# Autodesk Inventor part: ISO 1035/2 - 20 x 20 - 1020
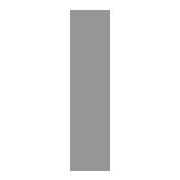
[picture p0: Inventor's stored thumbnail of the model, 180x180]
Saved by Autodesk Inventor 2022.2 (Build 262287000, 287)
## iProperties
IsCustomPart: 1
Created: 2021-02
Part Number: ISO 1035/2 - 20 x 20 - 1020
Material: Acciaio, Dolce
Description: Barre in acciaio laminate a caldo - Parte 2: barre quadre
Document SubType Name: Modeling
Standard: ISO 1035/2
Designer: 18907419
Standard Revision: First edition 1980-10-15
Standards Organization: ISO
Language: it-IT
Size Designation: 20x 20
Categories: <MemberInstance><Categories><Category DisplayName="Forme strutturali" InternalName="089c4875-fa83-4c05-b084-43b9cc11f5ed" Mnemonic="GRDR"><CategoryParameter Dis
Stock Number: 20x 20
Density: 7.85 g/cm^3
Appearance: Semilucidato
_CCFamilyMember: 168
_CCFamilyDisplayName: ISO 1035/2 - 1980 - Barre in acciaio laminate a caldo - Parte 2: barre quadre
_FrameMemberDoc: Frame Member File
_Version: 15.0.0
_GetPNFromCC: 1
G_L: 1020,000 mm
G_W: 20,000 mm
G_H: 20,000 mm
+9CC89346-D58E-49AB-A0AD-2FBC8E4EAC78+CUTDETAIL1: Angolo retto 45,00 gr
+2362145C-A886-4DE2-AF4E-FECAC0FDEC64+CUTDETAIL2: Angolo retto 45,00 gr
Author: 18907419
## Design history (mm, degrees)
node "Piano iniziale"
node "Piano finale"
sketch "Schizzo"
  geometry: L1 (10, -10)-(-10, -10); L2 (-10, -10)-(-10, 10); L3 (-10, 10)-(10, 10); L4 (10, 10)-(10, -10); L5 (-6, 0)-(8, 0); L6 (0, -30)-(0, 40); L7 (0, 54)-(0, -44) reference; L8 (-14, 0)-(14, 0) reference
  constraints: 12 end point, 2 collinear, 2 parallel, 1 horizontal, 1 perpendicular
  dimensions: "d0" = 20 distance between parallel lines of L3 L1 (= G_W); "d1" = 20 distance between parallel lines of L4 L2 (= G_H); "d4" = 10 distance between parallel lines of L6 L4 (= 0.5 x d1); "d5" = 10 distance between parallel lines of L5 L3 (= 0.5 x d0)
extrude "Corpo" new body sketch "Schizzo" stored distance "d2" = 1020 (= G_L); taper "d3" = 0 deg
node "Driven Length"
  sketch "Sketch3"
    geometry: L1 (0, 0)-(10, 0) reference
    constraints: 2 end point, 1 horizontal
  workplane "Work Plane3"
  sketch "Sketch4"
    geometry: L1 (-2, -10)-(12, -10) reference; L2 (-2, 1010)-(12, 1010) reference
    dimensions: "d9" = 1020 dimension on L1 L2 (derived)
node "Piano di lavoro4"
feature "Divisione1"
node "Piano di lavoro5"
feature "Divisione2"
body "Solid1"
other parameters: "G_W" = 20 [user parameter; used in 1 equation term], "G_H" = 20 [user parameter; used in 1 equation term], "G_L" = 1020 (= d9) [user parameter; used in 1 equation term], "d8" = 90 deg
